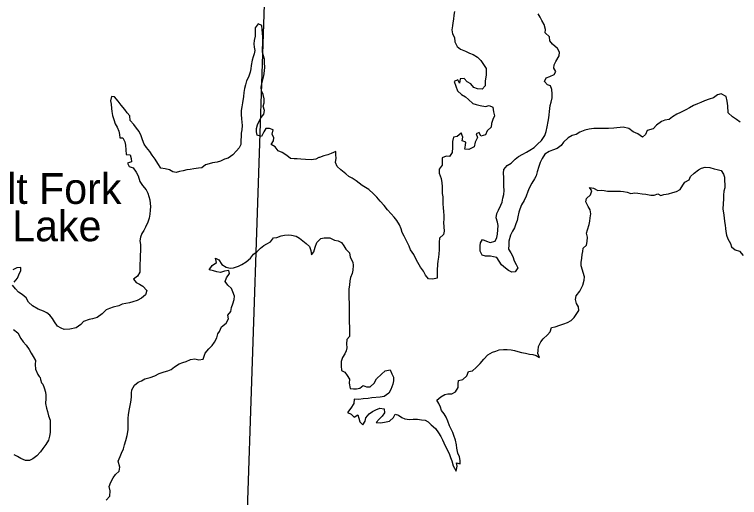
# Model space of a CAD drawing. Extents: x -29.6 to 34, y 0 to 22.
# Drawn here: x -22.275 to -20.183, y 9.088 to 10.482 of the extents above; entities that cross this region are included whole.
import ezdxf

# ---------------------------------------------------------------- set-up
doc = ezdxf.new("R2010")
doc.units = 0
for name, color, linetype in [('GM_X_Major_Lake', 7, 'Continuous'), ('GM_X_Major_Lake_Text', 7, 'Continuous'), ('GM_X_Township', 7, 'Continuous')]:
    doc.layers.add(name, color=color, linetype=linetype)

msp = doc.modelspace()

# ---------------------------------------------------------------- linework, layer by layer
at = {"layer": 'GM_X_Major_Lake'}
for points in [[(-21.0053, 10.4906), (-21.0073, 10.4795), (-21.0083, 10.4688), (-21.0096, 10.4581), (-21.011, 10.4489), (-21.013, 10.4378), (-21.0112, 10.4265), (-21.0057, 10.4151), (-21.0039, 10.4034), (-20.9974, 10.3896), (-20.9881, 10.3815), (-20.9738, 10.3756), (-20.9617, 10.3703), (-20.9514, 10.3661), (-20.9385, 10.3587), (-20.9296, 10.3489), (-20.9192, 10.3347), (-20.9134, 10.3255), (-20.9141, 10.3159), (-20.9143, 10.3066), (-20.9167, 10.2903), (-20.9166, 10.2764), (-20.9254, 10.2664), (-20.9385, 10.2677), (-20.9492, 10.2715), (-20.9582, 10.2818), (-20.9685, 10.287), (-20.9771, 10.2969), (-20.9892, 10.2958), (-20.9908, 10.2837), (-20.9952, 10.2929), (-21.0065, 10.2882), (-20.9963, 10.2612), (-20.9853, 10.251), (-20.9738, 10.2443), (-20.9645, 10.2369), (-20.9524, 10.2253), (-20.9431, 10.2225), (-20.931, 10.219), (-20.9161, 10.2166), (-20.9048, 10.2192), (-20.8948, 10.2143), (-20.8929, 10.2008), (-20.89, 10.1891), (-20.8949, 10.1791), (-20.898, 10.1673), (-20.8996, 10.157), (-20.9106, 10.1459), (-20.9162, 10.1345), (-20.9293, 10.1305), (-20.9336, 10.1411), (-20.9428, 10.1378), (-20.9385, 10.1265), (-20.9451, 10.1136), (-20.9489, 10.1001), (-20.9634, 10.0918), (-20.9758, 10.0931), (-20.9734, 10.1045), (-20.9721, 10.1134), (-20.9831, 10.1176), (-20.9811, 10.1279), (-20.9861, 10.1407), (-20.9861, 10.1396)], [(-20.8192, 9.9108), (-20.8223, 9.8976), (-20.8247, 9.8876), (-20.8282, 9.878), (-20.8323, 9.8662), (-20.8379, 9.8566), (-20.8432, 9.8452), (-20.848, 9.828), (-20.8486, 9.8167), (-20.8496, 9.8046), (-20.8424, 9.7936), (-20.837, 9.783), (-20.8326, 9.7712), (-20.8269, 9.7603), (-20.8229, 9.7503), (-20.8302, 9.7393), (-20.8398, 9.7381), (-20.8491, 9.7427), (-20.858, 9.7497), (-20.8691, 9.7596), (-20.8763, 9.7698), (-20.8831, 9.7805), (-20.8927, 9.7822), (-20.9016, 9.7839), (-20.9155, 9.7841), (-20.9258, 9.7876), (-20.9312, 9.7986), (-20.931, 9.8139), (-20.9303, 9.8231), (-20.924, 9.8321), (-20.9133, 9.8272), (-20.9026, 9.8234), (-20.8881, 9.8277), (-20.8832, 9.8381), (-20.8815, 9.8477), (-20.8799, 9.8598), (-20.8796, 9.873), (-20.8815, 9.8822), (-20.8848, 9.8946), (-20.8827, 9.9071), (-20.8782, 9.9167), (-20.8716, 9.9314), (-20.8677, 9.9403), (-20.8657, 9.9517), (-20.8633, 9.9624), (-20.862, 9.9741), (-20.8624, 9.9866), (-20.8632, 10.0011), (-20.863, 10.0118), (-20.8641, 10.0235), (-20.8632, 10.0346), (-20.8533, 10.046), (-20.8416, 10.0529), (-20.8304, 10.0644), (-20.8208, 10.0715), (-20.8081, 10.0784), (-20.7972, 10.0849), (-20.788, 10.0906), (-20.7756, 10.0975), (-20.7654, 10.1079), (-20.7541, 10.1183), (-20.7447, 10.1326), (-20.7408, 10.1444), (-20.7378, 10.1579), (-20.7347, 10.1725), (-20.7333, 10.1832), (-20.732, 10.1921), (-20.7307, 10.2021), (-20.7287, 10.2195), (-20.7263, 10.2288), (-20.7235, 10.2416), (-20.7233, 10.2526), (-20.7241, 10.2651), (-20.7277, 10.2761), (-20.7366, 10.2789), (-20.7459, 10.2887), (-20.741, 10.2991), (-20.7304, 10.3024), (-20.718, 10.3085), (-20.7131, 10.3174), (-20.7189, 10.3267), (-20.7179, 10.3363), (-20.7126, 10.3463), (-20.7028, 10.3623), (-20.7019, 10.373), (-20.7083, 10.384), (-20.7223, 10.396), (-20.7298, 10.4055), (-20.7313, 10.4176), (-20.7431, 10.4285), (-20.7425, 10.4382), (-20.7465, 10.4527), (-20.7534, 10.4644), (-20.7584, 10.4743), (-20.7638, 10.4839)], [(-21.3964, 10.0687), (-21.4052, 10.0645), (-21.4194, 10.0627), (-21.4353, 10.0629), (-21.4488, 10.0642), (-21.4595, 10.0648), (-21.4684, 10.0651), (-21.479, 10.0665), (-21.4894, 10.0753), (-21.503, 10.0834), (-21.514, 10.0886), (-21.5233, 10.1003), (-21.5348, 10.1069), (-21.5281, 10.1169), (-21.5264, 10.1259), (-21.5318, 10.1365), (-21.5287, 10.1486), (-21.5394, 10.1524), (-21.55, 10.1531), (-21.556, 10.1427), (-21.5626, 10.1295), (-21.5751, 10.1333), (-21.5766, 10.1433), (-21.5763, 10.1532), (-21.5739, 10.1632), (-21.5694, 10.1739), (-21.5631, 10.185), (-21.556, 10.1943), (-21.5536, 10.2043), (-21.5573, 10.2177), (-21.5545, 10.2267), (-21.5543, 10.2387), (-21.5576, 10.2512), (-21.5626, 10.2611), (-21.5634, 10.2718), (-21.5617, 10.2821), (-21.5586, 10.2935), (-21.5559, 10.3045), (-21.5532, 10.3195), (-21.5525, 10.3298), (-21.5533, 10.3423), (-21.5541, 10.3526), (-21.5563, 10.3622), (-21.5593, 10.3732), (-21.5594, 10.3845), (-21.5584, 10.3959), (-21.5585, 10.4077), (-21.5589, 10.4169), (-21.5597, 10.4283), (-21.5605, 10.439), (-21.5613, 10.4503), (-21.572, 10.4545), (-21.5808, 10.4438), (-21.5807, 10.4303), (-21.5809, 10.4189), (-21.5833, 10.4068), (-21.5843, 10.3972), (-21.5832, 10.3872), (-21.582, 10.3783), (-21.5834, 10.3687), (-21.5861, 10.3594), (-21.5893, 10.3502), (-21.5923, 10.3348)], [(-21.5923, 10.3348), (-21.5933, 10.3249), (-21.5947, 10.3153), (-21.6002, 10.301), (-21.6051, 10.2899), (-21.6086, 10.2785), (-21.6117, 10.2685), (-21.613, 10.2564), (-21.614, 10.2454), (-21.6174, 10.2265), (-21.6194, 10.2151), (-21.6211, 10.2052), (-21.621, 10.1931), (-21.6198, 10.1806), (-21.6187, 10.1714), (-21.6179, 10.1614), (-21.6192, 10.1486), (-21.6206, 10.139), (-21.6212, 10.1297), (-21.6218, 10.1194), (-21.6224, 10.1066), (-21.627, 10.097), (-21.6347, 10.088), (-21.6446, 10.0769), (-21.6583, 10.0669), (-21.669, 10.0639), (-21.6803, 10.0585), (-21.6898, 10.0556), (-21.7037, 10.0541), (-21.7136, 10.0504), (-21.7242, 10.0478), (-21.7341, 10.0396), (-21.7444, 10.0381), (-21.7575, 10.0362), (-21.7678, 10.0343), (-21.7774, 10.0332), (-21.7883, 10.031), (-21.7986, 10.0291), (-21.8082, 10.0255), (-21.8181, 10.0279), (-21.8281, 10.0332), (-21.8406, 10.0359), (-21.853, 10.0383), (-21.8613, 10.0514), (-21.8692, 10.0645), (-21.8775, 10.0755), (-21.885, 10.0864), (-21.8943, 10.0977), (-21.9012, 10.1076), (-21.9059, 10.1197), (-21.9092, 10.1318), (-21.9157, 10.1442), (-21.9228, 10.1537), (-21.9311, 10.164), (-21.9411, 10.1763), (-21.9423, 10.1891), (-21.9502, 10.1983), (-21.9563, 10.2079), (-21.967, 10.2206), (-21.976, 10.2319), (-21.9864, 10.2443), (-21.9953, 10.2449), (-21.998, 10.2328), (-21.9965, 10.2232), (-21.9954, 10.2104), (-21.9946, 10.2015), (-21.9924, 10.1905), (-21.9887, 10.1785), (-21.9851, 10.1667), (-21.9793, 10.1568), (-21.9742, 10.1451), (-21.9724, 10.1352), (-21.9712, 10.126), (-21.9624, 10.1257), (-21.9566, 10.1147), (-21.9547, 10.1047), (-21.9543, 10.0916), (-21.9528, 10.0781), (-21.9414, 10.0764), (-21.9388, 10.0661), (-21.9373, 10.0565), (-21.9486, 10.0529), (-21.944, 10.0433), (-21.9326, 10.0388), (-21.9243, 10.0264), (-21.9185, 10.0157), (-21.9131, 9.9998), (-21.9059, 9.9881), (-21.8948, 9.9754), (-21.8904, 9.9662), (-21.8872, 9.9566), (-21.8849, 9.9466), (-21.8834, 9.9367), (-21.883, 9.9278), (-21.8833, 9.9171), (-21.8846, 9.9057), (-21.8863, 9.8944), (-21.8901, 9.8822), (-21.8967, 9.8679), (-21.902, 9.8587), (-21.908, 9.8497)], [(-20.1808, 10.1714), (-20.1912, 10.1792), (-20.2033, 10.1862), (-20.2151, 10.1979), (-20.216, 10.2178), (-20.2186, 10.2313), (-20.2215, 10.2451), (-20.2351, 10.2528), (-20.2464, 10.2499), (-20.2577, 10.2409), (-20.2701, 10.2376), (-20.2832, 10.2329), (-20.2942, 10.2282), (-20.3037, 10.2239), (-20.315, 10.2188), (-20.3271, 10.2126), (-20.338, 10.2069), (-20.3532, 10.1993), (-20.3638, 10.1946), (-20.3759, 10.1867), (-20.3857, 10.1788), (-20.3978, 10.1765), (-20.4073, 10.1729), (-20.4222, 10.1628), (-20.432, 10.1517), (-20.4487, 10.1473), (-20.4535, 10.1352), (-20.4627, 10.1277), (-20.4763, 10.1375), (-20.4895, 10.1431), (-20.5023, 10.153), (-20.518, 10.1564), (-20.5272, 10.156), (-20.5364, 10.1545), (-20.5457, 10.1541), (-20.5609, 10.1525), (-20.5705, 10.1528), (-20.6035, 10.1525), (-20.6166, 10.1507), (-20.6287, 10.1477), (-20.6435, 10.1419), (-20.6541, 10.1358), (-20.6655, 10.1321), (-20.6775, 10.126), (-20.6902, 10.1135), (-20.6976, 10.1038), (-20.7089, 10.0955), (-20.7223, 10.0904), (-20.7322, 10.0861), (-20.7446, 10.0785), (-20.7523, 10.066), (-20.7575, 10.055), (-20.762, 10.0428), (-20.7665, 10.0279), (-20.7696, 10.0161), (-20.7745, 10.0072), (-20.7819, 9.995), (-20.7896, 9.9807), (-20.7938, 9.9707), (-20.7979, 9.9575), (-20.8046, 9.9447), (-20.8116, 9.9325), (-20.8171, 9.92), (-20.8192, 9.9108)], [(-20.9861, 10.1396), (-20.9978, 10.1292), (-21.0084, 10.1277), (-21.0108, 10.1153), (-21.0107, 10.1064), (-21.011, 10.0975), (-21.012, 10.0839), (-21.02, 10.0721), (-21.0293, 10.0728), (-21.0409, 10.0684), (-21.0405, 10.056), (-21.0404, 10.0471), (-21.0499, 10.0356), (-21.0495, 10.0235), (-21.0433, 10.0087), (-21.0418, 9.9959), (-21.0413, 9.9855), (-21.0409, 9.9767), (-21.0405, 9.9649), (-21.0393, 9.9557), (-21.0389, 9.9464), (-21.0388, 9.9347), (-21.038, 9.9247), (-21.0365, 9.9123), (-21.0361, 9.9027), (-21.036, 9.8913), (-21.0366, 9.881), (-21.0358, 9.8689), (-21.0346, 9.8568), (-21.037, 9.8472), (-21.0487, 9.8361), (-21.0496, 9.8251), (-21.0495, 9.8119), (-21.0498, 9.803), (-21.0501, 9.7909), (-21.0514, 9.7809), (-21.0531, 9.7703), (-21.0544, 9.761), (-21.0557, 9.7432), (-21.0549, 9.7308), (-21.0548, 9.7212), (-21.0676, 9.7179), (-21.08, 9.7185), (-21.0886, 9.7298)], [(-21.0886, 9.7298), (-21.0948, 9.7411), (-21.103, 9.7528), (-21.1106, 9.7659), (-21.1174, 9.7787), (-21.1228, 9.7886), (-21.1325, 9.8027), (-21.1365, 9.813), (-21.1409, 9.8229), (-21.1503, 9.8424), (-21.156, 9.8527), (-21.1593, 9.8633), (-21.164, 9.875), (-21.1716, 9.8874), (-21.1791, 9.8973), (-21.1877, 9.9069), (-21.1988, 9.9182), (-21.2085, 9.9309), (-21.2196, 9.9433), (-21.2296, 9.9546), (-21.2393, 9.9641), (-21.2529, 9.9768), (-21.2625, 9.9828), (-21.2714, 9.988), (-21.2804, 9.9951), (-21.2893, 10.0018), (-21.3007, 10.0092), (-21.31, 10.0144), (-21.3193, 10.0222), (-21.3332, 10.0334), (-21.3443, 10.0433), (-21.349, 10.0543), (-21.347, 10.0675), (-21.3478, 10.0771), (-21.3482, 10.086), (-21.3616, 10.0809), (-21.3712, 10.0769), (-21.3825, 10.074), (-21.3953, 10.0692), (-21.3964, 10.0687)], [(-20.6347, 9.7006), (-20.6305, 9.7145), (-20.6302, 9.7244), (-20.6401, 9.7567), (-20.6398, 9.7663), (-20.6381, 9.7784), (-20.6364, 9.7888), (-20.6351, 9.7977), (-20.6334, 9.8073), (-20.6246, 9.8162), (-20.6222, 9.8269), (-20.6216, 9.8394), (-20.6238, 9.8508), (-20.621, 9.8607), (-20.6162, 9.8757), (-20.6145, 9.885), (-20.6132, 9.8953), (-20.6118, 9.9067), (-20.6141, 9.9184), (-20.6191, 9.928), (-20.6263, 9.9407), (-20.6246, 9.9503), (-20.6126, 9.9611), (-20.6092, 9.9725), (-20.616, 9.9824), (-20.6039, 9.9804), (-20.5914, 9.9741), (-20.5822, 9.9749), (-20.573, 9.9742), (-20.5634, 9.9718), (-20.5492, 9.9723), (-20.5392, 9.9723), (-20.5261, 9.9717), (-20.5172, 9.9711), (-20.5065, 9.969), (-20.4962, 9.9656), (-20.4852, 9.9674), (-20.476, 9.9664), (-20.4632, 9.9644), (-20.4529, 9.963), (-20.439, 9.9603), (-20.4294, 9.9607), (-20.4188, 9.964), (-20.4099, 9.9595), (-20.4007, 9.9627), (-20.3879, 9.9643), (-20.3752, 9.9676), (-20.3642, 9.9708), (-20.3536, 9.9766), (-20.3462, 9.9891), (-20.3402, 9.9981), (-20.3275, 10.0042), (-20.324, 10.0138), (-20.3135, 10.0235), (-20.3011, 10.0336), (-20.2919, 10.0383), (-20.282, 10.0408), (-20.2678, 10.0399), (-20.2561, 10.0364), (-20.2472, 10.0343), (-20.2358, 10.0312), (-20.2286, 10.0213), (-20.2264, 10.0121), (-20.226, 10.0025), (-20.2248, 9.9904), (-20.2247, 9.9812), (-20.2278, 9.9715), (-20.2285, 9.9605), (-20.2284, 9.9488), (-20.2293, 9.936), (-20.2306, 9.9203), (-20.2288, 9.9093), (-20.2269, 9.8951), (-20.2261, 9.8848), (-20.2242, 9.8741), (-20.2234, 9.8645), (-20.2223, 9.8556), (-20.2197, 9.845), (-20.2161, 9.834), (-20.2085, 9.8205), (-20.2056, 9.8109), (-20.1956, 9.8021), (-20.1828, 9.7983), (-20.172, 9.7859)], [(-21.908, 9.8497), (-21.9118, 9.839), (-21.9131, 9.8283), (-21.912, 9.8177), (-21.9115, 9.8084), (-21.9111, 9.7995), (-21.9121, 9.7874), (-21.9123, 9.7753), (-21.9136, 9.7604), (-21.9135, 9.749), (-21.9131, 9.7376), (-21.9205, 9.7266), (-21.9321, 9.7176), (-21.9242, 9.708), (-21.9146, 9.7031), (-21.9049, 9.6972), (-21.8931, 9.6851), (-21.8969, 9.673), (-21.9086, 9.663), (-21.9213, 9.6565), (-21.9333, 9.6525), (-21.9429, 9.6495), (-21.9543, 9.6477), (-21.9642, 9.6455), (-21.9741, 9.6408), (-21.99, 9.6367), (-22.0014, 9.6331), (-22.0106, 9.6291), (-22.0225, 9.618), (-22.0363, 9.6068), (-22.0498, 9.6032), (-22.0593, 9.6013), (-22.0763, 9.5955), (-22.0841, 9.5866), (-22.0971, 9.5772), (-22.1156, 9.5735), (-22.1319, 9.5727), (-22.1408, 9.5765), (-22.1508, 9.5825), (-22.1601, 9.5948), (-22.1659, 9.6048), (-22.173, 9.614), (-22.1823, 9.6203), (-22.1919, 9.6255), (-22.2073, 9.6315), (-22.2237, 9.6413), (-22.2351, 9.6519), (-22.2412, 9.6636), (-22.253, 9.6734), (-22.2634, 9.6808), (-22.2723, 9.69), (-22.2806, 9.7006)], [(-21.6882, 9.5597), (-21.6831, 9.5666), (-21.6775, 9.5805), (-21.6644, 9.5905), (-21.6574, 9.603), (-21.6593, 9.6137), (-21.6512, 9.6244), (-21.6492, 9.6362), (-21.6447, 9.6469), (-21.6409, 9.6594), (-21.6402, 9.669), (-21.6446, 9.681), (-21.6489, 9.6906), (-21.6593, 9.7005), (-21.6668, 9.7111), (-21.6637, 9.7221), (-21.6549, 9.734), (-21.6568, 9.7428), (-21.6692, 9.741), (-21.6809, 9.737), (-21.6916, 9.739), (-21.7005, 9.7421), (-21.7133, 9.7445), (-21.7045, 9.757), (-21.6925, 9.766), (-21.6954, 9.7781), (-21.6854, 9.7736), (-21.6768, 9.7605), (-21.6643, 9.7524), (-21.6529, 9.7493), (-21.6434, 9.7504), (-21.6288, 9.7551), (-21.6193, 9.7598), (-21.6069, 9.7678), (-21.5942, 9.7782), (-21.5855, 9.79), (-21.5759, 9.7972), (-21.5654, 9.8072), (-21.5558, 9.8148), (-21.5466, 9.8202), (-21.5364, 9.8256), (-21.5273, 9.8367), (-21.518, 9.8385), (-21.5056, 9.8432), (-21.4961, 9.8451), (-21.4844, 9.8455), (-21.4755, 9.8449), (-21.4623, 9.8418), (-21.453, 9.8365), (-21.4338, 9.821), (-21.4234, 9.8119), (-21.4197, 9.8005), (-21.4179, 9.7881), (-21.4115, 9.797), (-21.4074, 9.8099), (-21.4022, 9.8234), (-21.3964, 9.8295)], [(-21.3964, 9.8295), (-21.3913, 9.8349), (-21.381, 9.8374), (-21.365, 9.8372), (-21.3515, 9.8306), (-21.3411, 9.8285), (-21.3312, 9.824), (-21.3243, 9.8144), (-21.3189, 9.8048), (-21.3079, 9.7943), (-21.306, 9.7818), (-21.2984, 9.7669), (-21.298, 9.757), (-21.2986, 9.7442), (-21.3003, 9.7346), (-21.3051, 9.7224), (-21.3072, 9.7128), (-21.3082, 9.7004), (-21.3102, 9.6904), (-21.308, 9.5528)], [(-22.2764, 9.7095), (-22.2666, 9.721), (-22.2624, 9.7303), (-22.2568, 9.7424), (-22.2565, 9.7517), (-22.2682, 9.7509), (-22.2799, 9.7451)], [(-20.7295, 9.5662), (-20.7256, 9.5779), (-20.715, 9.5804), (-20.7012, 9.5852), (-20.6899, 9.5888), (-20.6789, 9.5932), (-20.6686, 9.5986), (-20.6602, 9.6075), (-20.6461, 9.6276), (-20.6473, 9.6379), (-20.6534, 9.6481), (-20.6556, 9.6595), (-20.6536, 9.6702), (-20.6438, 9.6831), (-20.6347, 9.7006)], [(-22.2785, 9.5726), (-22.266, 9.5634), (-22.2568, 9.5464)], [(-21.0297, 9.3193), (-21.0355, 9.3296), (-21.0423, 9.3391), (-21.0455, 9.3487), (-21.0505, 9.3589), (-21.0563, 9.3688), (-21.045, 9.3785), (-21.0334, 9.3846), (-21.0242, 9.3868), (-21.0128, 9.3869), (-21.0019, 9.3923), (-20.9945, 9.4052), (-20.9946, 9.4144), (-20.9932, 9.4258), (-20.9816, 9.428), (-20.9696, 9.4387), (-20.9644, 9.4512), (-20.953, 9.4534), (-20.9428, 9.4631), (-20.9316, 9.4745), (-20.9207, 9.4867), (-20.909, 9.4995), (-20.896, 9.5067), (-20.8864, 9.51), (-20.8762, 9.5136), (-20.8642, 9.5148), (-20.8535, 9.5145), (-20.8415, 9.5135), (-20.8319, 9.5115), (-20.8223, 9.509), (-20.8117, 9.5066), (-20.8003, 9.5039), (-20.7889, 9.5015), (-20.7794, 9.5001), (-20.7698, 9.4977), (-20.7598, 9.4921), (-20.7645, 9.503), (-20.7642, 9.5123), (-20.7629, 9.5237), (-20.7562, 9.5372), (-20.7489, 9.5461), (-20.7369, 9.5569), (-20.7295, 9.5662)], [(-22.2568, 9.5464), (-22.25, 9.5365), (-22.2415, 9.527), (-22.2325, 9.515), (-22.2268, 9.5044), (-22.2211, 9.4948), (-22.215, 9.4832), (-22.2152, 9.4711), (-22.2148, 9.4576), (-22.2076, 9.4431), (-22.204, 9.4367), (-22.2015, 9.4339), (-22.2001, 9.4282), (-22.1968, 9.419), (-22.1936, 9.4144), (-22.1893, 9.4045), (-22.1857, 9.3921), (-22.1849, 9.3828), (-22.1852, 9.3733), (-22.1854, 9.359), (-22.1825, 9.3459), (-22.18, 9.3356), (-22.1767, 9.3236), (-22.1727, 9.3105), (-22.1723, 9.297), (-22.1722, 9.2852), (-22.1725, 9.2753), (-22.1738, 9.2646), (-22.1769, 9.2536), (-22.185, 9.2411), (-22.1934, 9.229), (-22.2004, 9.2193), (-22.211, 9.2075), (-22.2219, 9.1996), (-22.2318, 9.1949), (-22.2439, 9.1945), (-22.2574, 9.2001), (-22.267, 9.2061), (-22.2762, 9.2106)], [(-22.011, 9.0804), (-22.0001, 9.0915), (-21.9992, 9.1067), (-22.0017, 9.1195), (-21.9976, 9.1323), (-21.9902, 9.1441), (-21.9839, 9.1541), (-21.973, 9.1641), (-21.9716, 9.1751), (-21.9763, 9.1929), (-21.97, 9.2061), (-21.9659, 9.2153), (-21.9606, 9.2285), (-21.9575, 9.2399), (-21.9541, 9.2524), (-21.9503, 9.267), (-21.9475, 9.283), (-21.9472, 9.2933), (-21.9473, 9.3036), (-21.9467, 9.3171), (-21.9461, 9.3263), (-21.944, 9.3391), (-21.9413, 9.353), (-21.9392, 9.3626), (-21.9379, 9.3768), (-21.9373, 9.3889), (-21.9366, 9.3985), (-21.9293, 9.412), (-21.9183, 9.4203), (-21.9088, 9.4243), (-21.8989, 9.4304), (-21.8841, 9.434), (-21.8706, 9.4384), (-21.8572, 9.4456), (-21.8434, 9.4503), (-21.8325, 9.4532), (-21.8233, 9.4575), (-21.8138, 9.4647), (-21.7996, 9.4733), (-21.7897, 9.4773), (-21.7802, 9.4802), (-21.7675, 9.4864), (-21.7544, 9.4882), (-21.7427, 9.4851), (-21.731, 9.4873), (-21.7251, 9.5044), (-21.7142, 9.5166), (-21.705, 9.5266), (-21.698, 9.5362), (-21.691, 9.5487), (-21.6882, 9.5597)], [(-21.308, 9.5528), (-21.3157, 9.5436), (-21.3171, 9.5315), (-21.3159, 9.5201), (-21.318, 9.5109), (-21.3218, 9.502), (-21.3282, 9.4916), (-21.3323, 9.4806), (-21.3322, 9.4674), (-21.3311, 9.4543), (-21.3222, 9.4497), (-21.3151, 9.4398), (-21.3083, 9.4289), (-21.3096, 9.4175), (-21.3067, 9.4019), (-21.2971, 9.4009), (-21.2879, 9.4013), (-21.2787, 9.4035), (-21.2692, 9.4107), (-21.2592, 9.4068), (-21.2482, 9.4069), (-21.237, 9.4173), (-21.2303, 9.4298), (-21.2155, 9.4437), (-21.2053, 9.453), (-21.1912, 9.456), (-21.1865, 9.4443), (-21.1811, 9.4347), (-21.1814, 9.4241), (-21.1834, 9.4148), (-21.189, 9.3995), (-21.195, 9.3892), (-21.208, 9.3791), (-21.22, 9.3769), (-21.2441, 9.3753), (-21.2547, 9.3738), (-21.2689, 9.3723), (-21.2813, 9.3708), (-21.2944, 9.3711), (-21.2961, 9.359), (-21.3042, 9.3454), (-21.314, 9.3329), (-21.3037, 9.328), (-21.2944, 9.3192), (-21.2845, 9.3264), (-21.2809, 9.3165), (-21.2784, 9.3058), (-21.2695, 9.2974), (-21.2628, 9.3077), (-21.2614, 9.3173), (-21.252, 9.3291), (-21.2417, 9.3359), (-21.2322, 9.3406), (-21.2212, 9.3457), (-21.2081, 9.344), (-21.2077, 9.3319), (-21.2136, 9.3223), (-21.2228, 9.3137), (-21.2309, 9.3037), (-21.2185, 9.3034), (-21.2072, 9.3053), (-21.193, 9.3075), (-21.1817, 9.3186), (-21.1768, 9.3282), (-21.1669, 9.3251), (-21.1576, 9.3184), (-21.1484, 9.3146), (-21.1349, 9.3132), (-21.125, 9.314), (-21.1123, 9.3134), (-21.1002, 9.3117), (-21.0903, 9.3107), (-21.0814, 9.3058), (-21.0721, 9.297), (-21.0603, 9.2868), (-21.0514, 9.2747), (-21.0446, 9.2641), (-21.0399, 9.2542), (-21.0356, 9.245), (-21.0299, 9.233), (-21.0241, 9.222), (-21.0198, 9.2121), (-21.0166, 9.2029), (-21.0133, 9.1933), (-21.009, 9.1791), (-21.0004, 9.1636), (-20.9973, 9.1778), (-20.9991, 9.1874), (-20.9892, 9.1846), (-20.9885, 9.1949), (-20.9907, 9.2052), (-20.9954, 9.2155), (-20.9983, 9.2297), (-20.9991, 9.2396), (-21.002, 9.2534), (-21.0067, 9.2662), (-21.0103, 9.2754), (-21.015, 9.285), (-21.02, 9.2949), (-21.0243, 9.3076), (-21.0297, 9.3193)]]:
    msp.add_lwpolyline(points, dxfattribs=at)
at = {"layer": 'GM_X_Township'}
msp.add_lwpolyline([(-17.8742, 6.1253), (-19.1572, 6.1651), (-20.7391, 6.2042), (-21.4075, 6.2188), (-21.6713, 6.2244), (-21.6682, 6.402), (-21.6504, 7.1784), (-21.6499, 7.2446), (-21.6214, 8.5068), (-21.5392, 10.9421), (-21.5395, 10.9431), (-21.5399, 10.9443), (-21.5403, 10.9462), (-21.5405, 10.9479), (-21.5406, 10.9493), (-21.5407, 10.956), (-21.5408, 10.9609), (-21.5413, 10.9689), (-21.5414, 10.9701), (-19.4178, 10.9099), (-18.9861, 10.8993), (-17.4554, 10.8405)], dxfattribs=at)

# ---------------------------------------------------------------- texts
at = {"layer": 'GM_X_Major_Lake_Text'}
for s, rotation, p in [('Salt Fork', 0.0035, (-22.4417, 9.9351)), ('Lake', 0.0018, (-22.2817, 9.8273))]:
    msp.add_text(s, height=0.08878, rotation=rotation, dxfattribs=at).set_placement(p)

doc.saveas('drawing.dxf')
